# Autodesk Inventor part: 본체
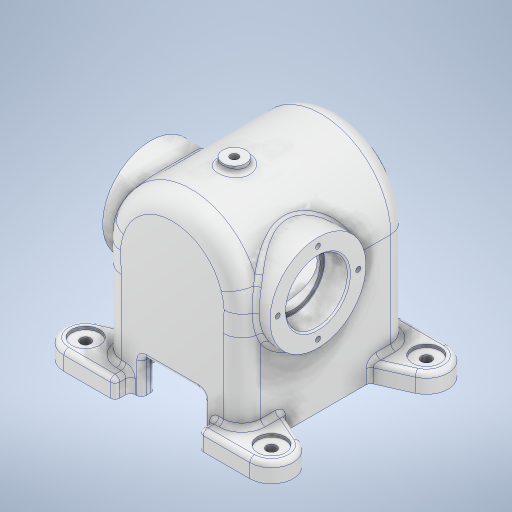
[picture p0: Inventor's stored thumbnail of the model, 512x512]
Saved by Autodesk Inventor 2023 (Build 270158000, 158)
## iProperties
Created: 2024-09
Part Number: 본체
Material: 알루미늄 6061
Document SubType Name: Modeling
Designer: asung
Density: 2.7 g/cm^3
Appearance: 알루미늄 - 평지
Mass: 1386.57 g
Surface Area: 1149.27 cm^2
Volume: 513.544 cm^3
Author: asung
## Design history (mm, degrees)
sketch "스케치1"
  geometry: C1 r 45 at (0, 0); 1 further point
  constraints: 1 centre point, 1 coincident
  dimensions: "d0" = 90 diameter of C1
extrude "돌출1" new body sketch "스케치1" distance "d1" = 108; taper "d2" = 0 deg
sketch "스케치2"
  geometry: C1 r 28.5 at (0, 0); 1 further point
  constraints: 1 centre point, 1 coincident
  dimensions: "d3" = 57 diameter of C1
extrude "돌출2" join sketch "스케치2" distance "d4" = 6; taper "d5" = 0 deg
sketch "스케치3"
  geometry: L1 (45, 108)-(45, 0) reference; L2 (45, 0)-(28.5, 0) reference; L3 (28.5, 0)-(28.5, -6) reference; L4 (28.5, -6)-(-28.5, -6) reference; L5 (-28.5, -6)-(-28.5, 0) reference; L6 (-28.5, 0)-(-45, 0) reference; L7 (-45, 0)-(-45, 108) reference; L8 (-45, 108)-(45, 108) reference; C1 r 7.5 at (0, 68); 1 further point
  constraints: 1 centre point, 1 vertical alignment
  dimensions: "d6" = 15 diameter of C1; "d7" = 74 distance from line of C1.centre L4
extrude "돌출3" join sketch "스케치3" stored distance "d8" = 98; taper "d9" = 0 deg
sketch "스케치4"
  geometry: L1 (-28.5, -6)-(-28.5, 0) reference; L2 (-28.5, 0)-(-45, 0) reference; L3 (-45, 0)-(-45, 60.5) reference; L4 (-45, 60.5)-(-49, 60.5) reference; L5 (-49, 60.5)-(-49, 75.5) reference; L6 (-49, 75.5)-(-45, 75.5) reference; L7 (-45, 75.5)-(-45, 108) reference; L8 (-45, 108)-(45, 108) reference; L9 (45, 108)-(45, 75.5) reference; L10 (45, 75.5)-(49, 75.5) reference; L11 (49, 75.5)-(49, 60.5) reference; L12 (49, 60.5)-(45, 60.5) reference; L13 (45, 60.5)-(45, 0) reference; L14 (45, 0)-(28.5, 0) reference; L15 (28.5, 0)-(28.5, -6) reference; L16 (28.5, -6)-(-28.5, -6) reference; C1 r 31 at (0, 68); 2 further points
  constraints: 1 centre point, 1 horizontal alignment, 1 midpoint, 1 vertical alignment
  dimensions: "d10" = 62 diameter of C1
  node "절단 모서리 투영2"
sketch "스케치5"
  geometry: 1 further point
sketch "스케치6"
  geometry: L1 (-28.5, -6)-(-28.5, 0) reference; L2 (-28.5, 0)-(-45, 0) reference; L3 (-45, 0)-(-45, 60.5) reference; L4 (-45, 60.5)-(-49, 60.5) reference; L5 (-49, 60.5)-(-49, 75.5) reference; L6 (-49, 75.5)-(-45, 75.5) reference; L7 (-45, 75.5)-(-45, 108) reference; L8 (-45, 108)-(45, 108) reference; L9 (45, 108)-(45, 75.5) reference; L10 (45, 75.5)-(49, 75.5) reference; L11 (49, 75.5)-(49, 60.5) reference; L12 (49, 60.5)-(45, 60.5) reference; L13 (45, 60.5)-(45, 0) reference; L14 (45, 0)-(28.5, 0) reference; L15 (28.5, 0)-(28.5, -6) reference; L16 (28.5, -6)-(-28.5, -6) reference; L17 (36, 66.5)-(36, 96); L18 (33, 99)-(-36, 99); L19 (-36, 99)-(-36, 69.5); L20 (-36, 69.5)-(-36, 9); L21 (-36, 9)-(-19.5, 9); L22 (19.5, 9)-(33, 9); L23 (36, 12)-(36, 96); L24 (19.5, 9)-(-19.5, 9); L25 (45, 108)-(-45, 108) reference; L26 (0, 108)-(0, 0); A1 r 3 centre (33, 96) between (36, 96) and (33, 99); A2 r 3 centre (33, 96) between (36, 96) and (33, 99); A3 r 3 centre (33, 12) between (33, 9) and (36, 12); 2 further points
  constraints: 18 end point, 6 point on circle, 6 tangent, 3 centre point, 2 point on line, 1 concentric, 1 horizontal, 1 midpoint, 1 vertical, 5 other
  dimensions: "d13" = 9 distance between parallel lines of L9 L17; "d14" = 3 radius of A1; "d15" = 3 radius of A3 (derived)
revolve "회전1" sketch "스케치6" stored, may be unused: angle "d16" = 90 deg
sketch "스케치7"
  geometry: 1 further point
hole "구멍1" sketch "스케치7" at (0, 0) diameter "d17" = 33; stored, may be unused: countersink angle "d21" = 90 deg, drill point angle "d23" = 118 deg; dims "d18" = 11, "d19" = 4, "d20" = 2, "d22" = 16
node "작업 평면2"
node "작업 평면3"
sketch "스케치10"
  geometry: C1 r 7.5 at (0, 0) reference; 1 further point
hole "구멍4" sketch "스케치10" at (0, 0) diameter "d38" = 5.1881; stored, may be unused: countersink angle "d42" = 90 deg, drill point angle "d44" = 118 deg; dims "d39" = 15, "d40" = 40, "d41" = 16, "d43" = 16
sketch "스케치11"
  geometry: C1 r 7.5 at (0, 0) reference; 1 further point
hole "구멍5" sketch "스케치11" at (0, 0) diameter "d45" = 5.1881; stored, may be unused: countersink angle "d49" = 90 deg, drill point angle "d51" = 118 deg; dims "d46" = 15, "d47" = 4, "d48" = 2, "d50" = 16
node "작업 평면4"
sketch "스케치13"
  geometry: L1 (0, 0)-(0, 23)
  constraints: 2 end point, 1 vertical
  dimensions: "d63" = 23 distance of L1.start L1.end
hole "구멍7" sketch "스케치13" at (0, 23) diameter "d64" = 3.242; stored, may be unused: countersink angle "d68" = 90 deg, drill point angle "d70" = 118 deg; dims "d65" = 8, "d66" = 4, "d67" = 2, "d69" = 10
node "작업 평면1"
sketch "스케치14"
  geometry: L1 (-60, -50)-(60, -50); L2 (60, -50)-(60, 78); L3 (60, 78)-(-60, 78); L4 (-60, 78)-(-60, -50); L5 (-60, -50)-(60, 78); L6 (60, -50)-(-60, 78); L7 (-45, -40)-(45, -40) reference; L8 (-60, -36)-(60, -36); L9 (60, 64)-(-60, 64); L10 (60, -50)-(27, -50); L11 (27, -50)-(27, -36); L12 (65.693, -23.21)-(45, -14); L13 (45, 68)-(45, -40) reference; L14 (60, 14)-(85.179, 14); L15 (60, 78)-(27, 78); L16 (27, 78)-(27, 64); L17 (65.693, 51.21)-(45, 42); L18 (0, -50)-(0, -59.804); L19 (-45, 68)-(-45, -40) reference; L20 (-45, 68)-(45, 68) reference; L21 (-60, -50)-(-27, -50); L22 (-60, 78)-(-27, 78); L23 (-27, -50)-(-27, -36); L24 (-65.693, -23.21)-(-45, -14); L25 (-65.693, 51.21)-(-45, 42); L26 (-27, 78)-(-27, 64); L27 (36, -40)-(36, 59); L28 (36, 59)-(-36, 59); L29 (-36, 59)-(-36, -40); L30 (-45, -31)-(45, -31); A1 r 14 centre (60, -36) between (60, -50) and (65.693, -23.21); A2 r 14 centre (60, 64) between (65.693, 51.21) and (60, 78); A3 r 14 centre (-60, 64) between (-65.693, 51.21) and (-60, 78); 14 further points
  constraints: 52 end point, 14 symmetric about line, 6 point on circle, 5 parallel, 4 midpoint, 4 point on line, 3 centre point, 2 coincident, 2 horizontal, 2 perpendicular, 1 tangent, 1 vertical, 1 vertical alignment, 7 other
  dimensions: "d75" = 120 distance of L3.end L2.end; "d76" = 128 distance of L2.end L1.end; "d77" = 10 distance between parallel lines of L7 L1; "d78" = 14 distance between parallel lines of L1 L8; "d79" = 14 distance between parallel lines of L3 L9; "d80" = 28 diameter of A1; "d81" = 18 distance between parallel lines of L13 L11; "d82" = 36 vertical distance of L12.end L1.end; "d83" = 40.17924 distance from line of L14.end L13; "d84" = 15 distance from line of L9.start L13; "d85" = 24.7897 distance from line of point (20.21, -50) L13; "d86" = 127.80376 distance from line of L18.end L20; "d87" = 105 distance from line of L9.end L13; "d88" = 105 distance from line of L8.start L13; "d89" = 9 distance between parallel lines of L13 L27; "d90" = 9 distance between parallel lines of L7 L30
extrude "돌출5" join sketch "스케치14" distance "d91" = 12; taper "d92" = 0 deg
sketch "스케치15"
  geometry: L1 (36, -31)-(36, 59) reference; L2 (36, 59)-(-36, 59) reference; L3 (-36, 59)-(-36, -31) reference; L4 (-36, -31)-(36, -31) reference; L5 (45, -14)-(65.693, -23.21) reference; L6 (60, -50)-(27, -50) reference; L7 (27, -50)-(27, -40) reference; L8 (27, -40)-(-27, -40) reference; L9 (-27, -40)-(-27, -50) reference; L10 (-27, -50)-(-60, -50) reference; L11 (-65.693, -23.21)-(-45, -14) reference; L12 (-45, -14)-(-45, 42) reference; L13 (-45, 42)-(-65.693, 51.21) reference; L14 (-60, 78)-(-27, 78) reference; L15 (-27, 78)-(-27, 68) reference; L16 (-27, 68)-(27, 68) reference; L17 (27, 68)-(27, 78) reference; L18 (27, 78)-(60, 78) reference; L19 (65.693, 51.21)-(45, 42) reference; L20 (45, 42)-(45, -14) reference; L21 (-45, -40)-(-45, 68); L22 (-45, 68)-(45, 68); L23 (45, 68)-(45, -40); L24 (45, -40)-(-45, -40); A1 r 14 centre (60, -36) between (60, -50) and (65.693, -23.21) reference; A2 r 14 centre (-60, -36) between (-65.693, -23.21) and (-60, -50) reference; A3 r 14 centre (-60, 64) between (-60, 78) and (-65.693, 51.21) reference; A4 r 14 centre (60, 64) between (65.693, 51.21) and (60, 78) reference; 9 further points
  constraints: 8 end point, 3 other
  dimensions: "d93" = 90 distance of L23.end L21.start
extrude "돌출6" join sketch "스케치15" stored distance "d94" = 12; taper "d95" = 0 deg
sketch "스케치16"
  geometry: L1 (-20, -53)-(20, -53); L2 (20, -53)-(20, -76); L3 (20, -76)-(-20, -76); L4 (-20, -76)-(-20, -53); L5 (-20, -53)-(20, -76); L6 (20, -53)-(-20, -76); L7 (-27, -76)-(27, -76) reference; 3 further points
  constraints: 12 end point, 4 midpoint, 2 parallel, 1 horizontal, 1 perpendicular
  dimensions: "d96" = 40 distance of L2.end L3.end; "d97" = 23 distance of L1.end L2.end
extrude "돌출7" cut sketch "스케치16" extent not by distance; stored distance "d98" = 0; taper "d99" = 0 deg
sketch "스케치17"
  geometry: L1 (74, -76)-(60, -76) reference; 3 further points
  constraints: 1 vertical alignment, 1 other
  dimensions: "d100" = 35 distance from line of L1 point (0, -41)
feature "엠보싱1" sketch "스케치17" dims "d101" = 0.5, "d102" = 0
sketch "스케치18"
  geometry: L1 (-27, -40)-(-45, -40) reference; L2 (-45, -40)-(-45, -14) reference; L3 (-45, -14)-(-65.693, -23.21) reference; L4 (-60, -50)-(-27, -50) reference; L5 (-27, -50)-(-27, -40) reference; L6 (-45, 68)-(-27, 68) reference; L7 (-27, 68)-(-27, 78) reference; L8 (-27, 78)-(-60, 78) reference; L9 (-65.693, 51.21)-(-45, 42) reference; L10 (-45, 42)-(-45, 68) reference; L11 (45, 68)-(45, 42) reference; L12 (45, 42)-(65.693, 51.21) reference; L13 (60, 78)-(27, 78) reference; L14 (27, 78)-(27, 68) reference; L15 (27, 68)-(45, 68) reference; L16 (45, -14)-(45, -40) reference; L17 (45, -40)-(27, -40) reference; L18 (27, -40)-(27, -50) reference; L19 (27, -50)-(60, -50) reference; L20 (65.693, -23.21)-(45, -14) reference; A1 r 14 centre (-60, -36) between (-65.693, -23.21) and (-60, -50) reference; A2 r 14 centre (-60, 64) between (-60, 78) and (-65.693, 51.21) reference; A3 r 14 centre (60, 64) between (65.693, 51.21) and (60, 78) reference; A4 r 14 centre (60, -36) between (60, -50) and (65.693, -23.21) reference; 1 further point
hole "구멍8" sketch "스케치18" at (-60, -36), (60, -36), (60, 64), (-60, 64) diameter "d103" = 6.6; stored, may be unused: countersink angle "d107" = 90 deg, drill point angle "d109" = 118 deg; dims "d104" = 6, "d105" = 18, "d106" = 2, "d108" = 8
node "작업 평면5"
sketch "스케치19"
  geometry: L1 (0, 0)-(0, 108) reference; L2 (-28.5, -6)-(28.5, -6) reference; C1 r 31 at (0, 68)
  constraints: 1 centre point, 1 point on line
  dimensions: "d111" = 62 diameter of C1; "d112" = 74 distance from line of L2 C1.centre
extrude "돌출8" join sketch "스케치19" stored distance "d113" = 10; taper "d114" = 0 deg
sketch "스케치20"
  geometry: C1 r 31 at (0, 0) reference; 2 further points
  constraints: 1 coincident
hole "구멍9" sketch "스케치20" at (0, 0) diameter "d115" = 35; stored, may be unused: countersink angle "d119" = 90 deg, drill point angle "d121" = 118 deg; dims "d116" = 6, "d117" = 40, "d118" = 16, "d120" = 8
sketch "스케치21"
  geometry: C1 r 31 at (0, 0) reference; 2 further points
  constraints: 1 coincident
hole "구멍10" sketch "스케치21" at (0, 0) diameter "d122" = 35; stored, may be unused: countersink angle "d126" = 90 deg, drill point angle "d128" = 118 deg; dims "d123" = 6, "d124" = 40, "d125" = 16, "d127" = 8
sketch "스케치22"
  geometry: L1 (0, 0)-(0, 26); C1 r 31 at (0, 0) reference; 1 further point
  constraints: 2 end point, 1 vertical
  dimensions: "d129" = 26 distance of L1.start L1.end
hole "구멍11" sketch "스케치22" at (0, 26) diameter "d130" = 3.242; stored, may be unused: countersink angle "d134" = 90 deg, drill point angle "d136" = 118 deg; dims "d131" = 8, "d132" = 40, "d133" = 16, "d135" = 10
chamfer "모따기1" distance "d140" = 1; stored, may be unused: second distance "d141" = 2, angle "d142" = 45 deg
fillet "모깎기1" dims "d143" = 0.3
fillet "모깎기2" dims "d144" = 12
fillet "모깎기3" dims "d145" = 3
fillet "모깎기4" dims "d146" = 3
fillet "모깎기5" dims "d147" = 3
sketch "스케치23"
  geometry: 1 further point
node "솔리드1"
pattern_circular "원형 패턴2" dims angle "d72" = 360 deg
mirror "미러2"
pattern_circular "원형 패턴3" dims angle "d138" = 360 deg
mirror "미러3"
node "투영된 루프3"
node "투영된 루프4"
node "투영된 루프6"
node "투영된 루프7"
node "투영된 루프8"
node "투영된 루프9"
node "절단 모서리 투영1"
node "절단 모서리 투영3"
node "절단 모서리 투영4"
feature "A9D066F2-1C7D-4E18-AEED-F7BC21143FA4" dims "d17" = 33, "d18" = 11, "d19" = 4, "d20" = 2, "d21" = 90 deg, "d22" = 16, "d23" = 118 deg
other parameters: "d74" = -125, "d110" = 54
